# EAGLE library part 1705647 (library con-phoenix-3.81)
MKDSD 1,5/12-3,81 Printklemme Nennstrom: 8 A Bemessungsspannung: 200 V Raster: 3,81 mm Polzahl: 12 Montageart: Löten Anschlussart: Schraubanschluss Anschlussrichtung vom Leiter zur Platine: 0° Source: http://eshop.phoenixcontact.com .. 1705647.pdf
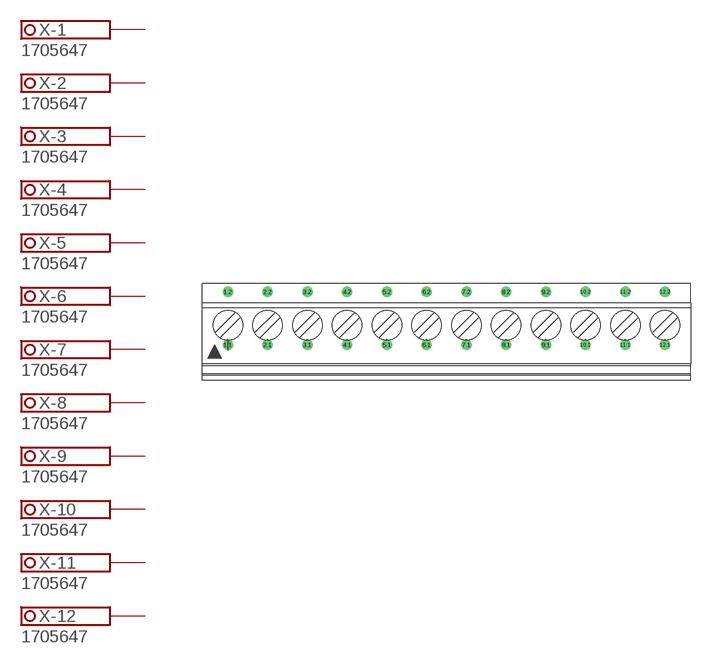
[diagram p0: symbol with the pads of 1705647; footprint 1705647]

Designator prefix X; gates -1=SCHRAUBKLEMME_2 -2=SCHRAUBKLEMME_2 -3=SCHRAUBKLEMME_2 -4=SCHRAUBKLEMME_2 -5=SCHRAUBKLEMME_2 -6=SCHRAUBKLEMME_2 -7=SCHRAUBKLEMME_2 -8=SCHRAUBKLEMME_2 -9=SCHRAUBKLEMME_2 -10=SCHRAUBKLEMME_2 -11=SCHRAUBKLEMME_2 -12=SCHRAUBKLEMME_2

## 1705647 (OC_FARNELL: unknown; OC_NEWARK: unknown)  [1705647]
1.1  -1:1A  pas
1.2  -1:1B  pas
2.1  -2:1A  pas
2.2  -2:1B  pas
3.1  -3:1A  pas
3.2  -3:1B  pas
4.1  -4:1A  pas
4.2  -4:1B  pas
5.1  -5:1A  pas
5.2  -5:1B  pas
6.1  -6:1A  pas
6.2  -6:1B  pas
7.1  -7:1A  pas
7.2  -7:1B  pas
8.1  -8:1A  pas
8.2  -8:1B  pas
9.1  -9:1A  pas
9.2  -9:1B  pas
10.1  -10:1A  pas
10.2  -10:1B  pas
11.1  -11:1A  pas
11.2  -11:1B  pas
12.1  -12:1A  pas
12.2  -12:1B  pas

## Footprint 1705647 (pad centres in mm)
MKDSD 1,5/12-3,81 Printklemme Nennstrom: 8 A Bemessungsspannung: 200 V Raster: 3,81 mm Polzahl: 12 Montageart: Löten Anschlussart: Schraubanschluss Anschlussrichtung vom Leiter zur Platine: 0°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
drill 0.5 pad 0.9 round: 1.1 -20.955,-1.25; 1.2 -20.955,3.83; 2.1 -17.145,-1.25; 2.2 -17.145,3.83; 3.1 -13.335,-1.25; 3.2 -13.335,3.83; 4.1 -9.525,-1.25; 4.2 -9.525,3.83; 5.1 -5.715,-1.25; 5.2 -5.715,3.83; 6.1 -1.905,-1.25; 6.2 -1.905,3.83; 7.1 1.905,-1.25; 7.2 1.905,3.83; 8.1 5.715,-1.25; 8.2 5.715,3.83; 9.1 9.525,-1.25; 9.2 9.525,3.83; 10.1 13.335,-1.25; 10.2 13.335,3.83; 11.1 17.145,-1.25; 11.2 17.145,3.83; 12.1 20.955,-1.25; 12.2 20.955,3.83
